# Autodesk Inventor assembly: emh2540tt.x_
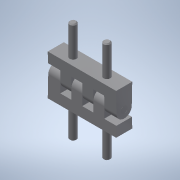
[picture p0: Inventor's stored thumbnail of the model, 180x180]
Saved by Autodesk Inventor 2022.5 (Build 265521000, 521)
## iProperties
Part Number: emh2540tt.x_
Material: 一般
Document SubType Name: Assembly
Designer: ImaoCorp
Sending System: SOLIDWORKS 2017-2017317
MC: AMD64
MC_MODEL: Intel64 Family 6 Model 60 Stepping 3, GenuineIntel
OS: Windows_NT
FRU: Parasolid Version 29.0, build 201,  4-17-2017
FORMAT: text
GUISE: transmit
KEY: emh2540tt
FILE: emh2540tt.x_t
DATE: Mon May 13 14:20:42 2019
Author: ImaoCorp
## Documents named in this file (4)
- X:\14_SW2022-Inv2022\00_全2023-1023新製品(TCC)まで\e\emh2540tt\EMH2540TT.iam
- X:\14_SW2022-Inv2022\00_全2023-1023新製品(TCC)まで\e\emh2540tt\emh2540tt_01.ipt
- X:\14_SW2022-Inv2022\00_全2023-1023新製品(TCC)まで\e\emh2540tt\emh2540tt_02.ipt
- X:\14_SW2022-Inv2022\00_全2023-1023新製品(TCC)まで\e\emh2540tt\emh2540tt_03.ipt
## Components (3 placed, 3 different names)
1. emh2540tt_01
2. emh2540tt_02
3. emh2540tt_03
